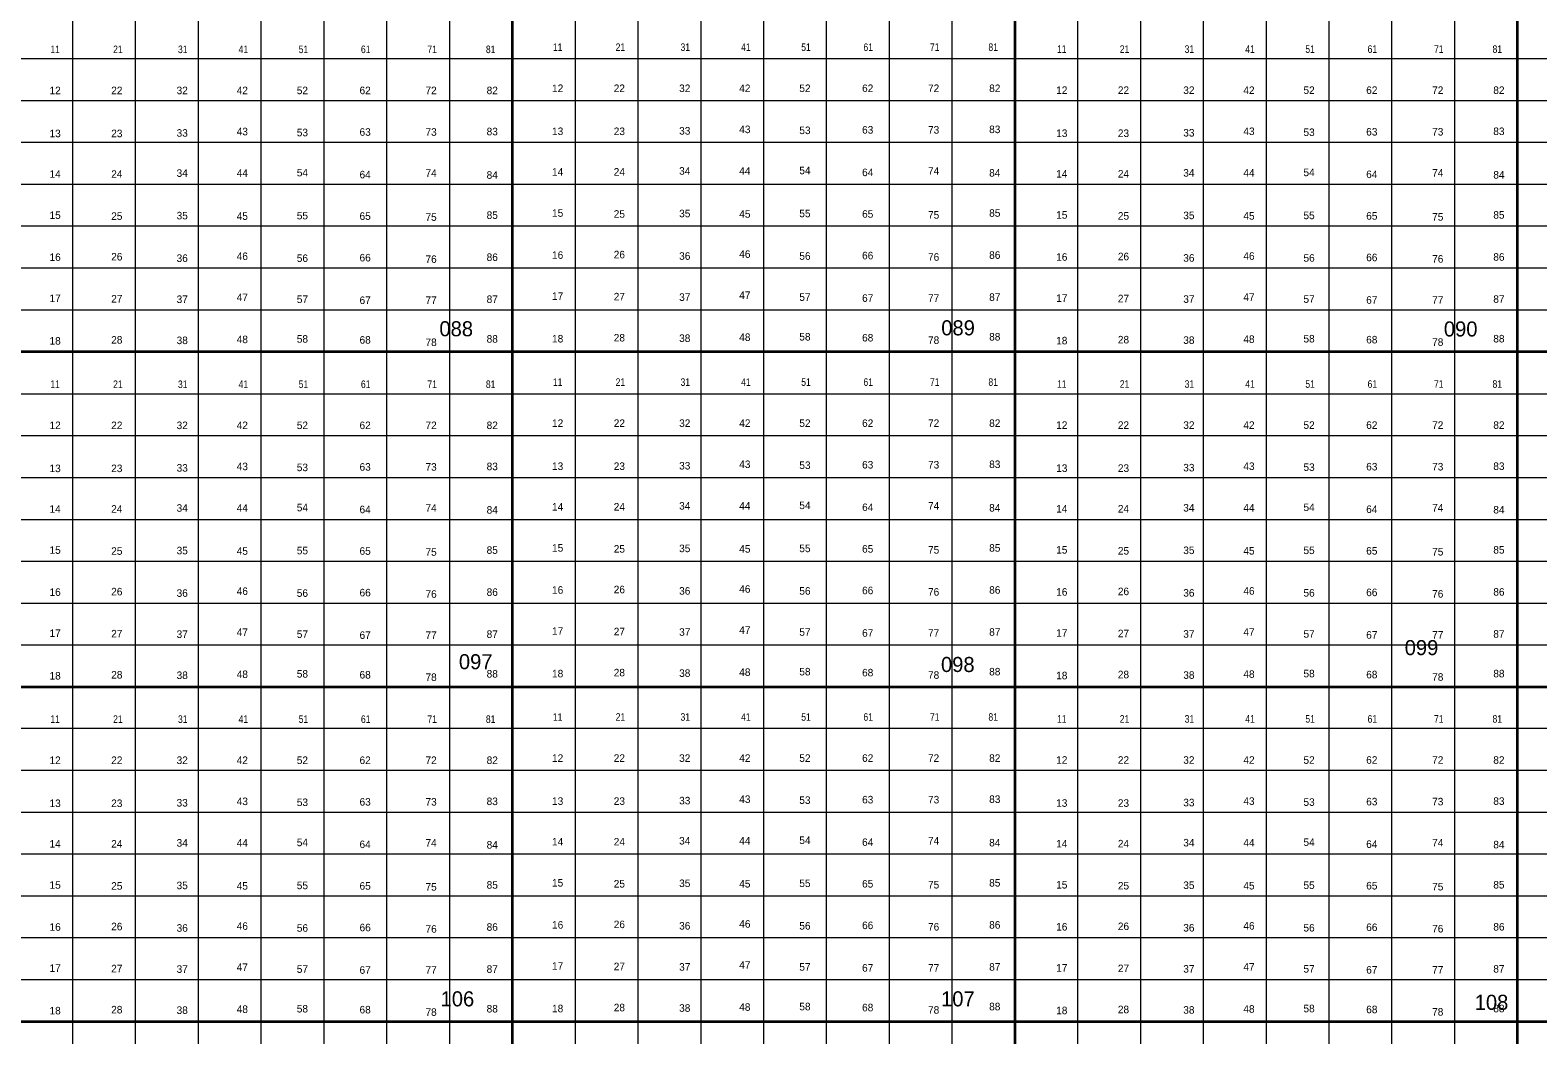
# Model space of a CAD drawing. Extents: x 639000 to 672000, y 222000 to 252000.
# Drawn here: x 651120 to 660121, y 227921 to 233921 of the extents above; entities that cross this region are included whole.
import ezdxf
from ezdxf.enums import TextEntityAlignment as Align

# ---------------------------------------------------------------- set-up
doc = ezdxf.new("R2010")
doc.units = 0
doc.header["$LTSCALE"] = 18
doc.layers.add('1', color=7, linetype='Continuous', lineweight=13)
doc.layers.add('2', color=7, linetype='Continuous')
doc.layers.add('29', color=7, linetype='Continuous')

msp = doc.modelspace()

# ---------------------------------------------------------------- linework, layer by layer
at = {"layer": '1'}
for p, q in [((651375, 224000), (651375, 252000)), ((651750, 224000), (651750, 252000)), ((652125, 224000), (652125, 252000)), ((652500, 224000), (652500, 252000)), ((652875, 224000), (652875, 252000)), ((653250, 224000), (653250, 252000)), ((653625, 224000), (653625, 252000)), ((654375, 222000), (654375, 252000)), ((654750, 222000), (654750, 252000)), ((655125, 222000), (655125, 252000)), ((655500, 222000), (655500, 252000)), ((655875, 222000), (655875, 252000)), ((656250, 222000), (656250, 252000)), ((656625, 222000), (656625, 252000)), ((657375, 222000), (657375, 248000)), ((657750, 222000), (657750, 248000)), ((658125, 222000), (658125, 248000)), ((658500, 222000), (658500, 248000)), ((658875, 222000), (658875, 248000)), ((659250, 222000), (659250, 248000)), ((659625, 222000), (659625, 248000)), ((669000, 233750), (642000, 233750)), ((669000, 233500), (642000, 233500)), ((669000, 233250), (642000, 233250)), ((669000, 233000), (642000, 233000)), ((669000, 232750), (642000, 232750)), ((669000, 232500), (642000, 232500)), ((669000, 232250), (642000, 232250)), ((642000, 231750), (669000, 231750)), ((642000, 231500), (669000, 231500)), ((642000, 231250), (669000, 231250)), ((642000, 231000), (669000, 231000)), ((642000, 230750), (669000, 230750)), ((642000, 230500), (669000, 230500)), ((642000, 230250), (669000, 230250)), ((663000, 229750), (642000, 229750)), ((663000, 229500), (642000, 229500)), ((663000, 229250), (642000, 229250)), ((663000, 229000), (642000, 229000)), ((663000, 228750), (642000, 228750)), ((663000, 228500), (642000, 228500)), ((663000, 228250), (642000, 228250))]:
    msp.add_line(p, q, dxfattribs=at)
at = {"layer": '1', "lineweight": 35}
for p, q in [((654000, 222000), (654000, 252000)), ((657000, 222000), (657000, 252000)), ((660000, 222000), (660000, 248000)), ((669000, 232000), (642000, 232000)), ((642000, 230000), (669000, 230000)), ((663000, 228000), (642000, 228000))]:
    msp.add_line(p, q, dxfattribs=at)

# ---------------------------------------------------------------- texts
at = {"layer": '2'}
for s, p in [('088', (653663.61, 232093.25)), ('089', (656659.61, 232098.74)), ('090', (659660.01, 232091.88)), ('099', (659426.17, 230189.03)), ('097', (653779.93, 230104.88)), ('098', (656657.97, 230088.3)), ('106', (653670.76, 228091.57)), ('107', (656658.37, 228091.57))]:
    msp.add_text(s, height=90, rotation=359.94, dxfattribs=at).set_placement(p, align=Align.CENTER)
msp.add_text('108', height=90, dxfattribs=at).set_placement((659844.15, 228070.86), align=Align.CENTER)
at = {"layer": '29', "width": 0.85}
for s, p in [('11', (654269.27, 233797.21)), ('21', (654643.88, 233797.21)), ('31', (655031.18, 233797.21)), ('41', (655393.08, 233797.21)), ('51', (655751.81, 233797.21)), ('61', (656123.24, 233797.21)), ('71', (656520.07, 233797.21)), ('81', (656869.28, 233797.21)), ('11', (651269.26, 233784.35)), ('21', (651643.86, 233784.35)), ('31', (652031.16, 233784.35)), ('41', (652393.07, 233784.35)), ('51', (652751.8, 233784.35)), ('61', (653123.23, 233784.35)), ('71', (653520.05, 233784.35)), ('81', (653869.26, 233784.35)), ('11', (657278.8, 233785.66)), ('21', (657653.4, 233785.66)), ('31', (658040.7, 233785.66)), ('41', (658402.61, 233785.66)), ('51', (658761.34, 233785.66)), ('61', (659132.77, 233785.66)), ('71', (659529.6, 233785.66)), ('81', (659878.8, 233785.66)), ('11', (651269.26, 231784.35)), ('21', (651643.86, 231784.35)), ('31', (652031.16, 231784.35)), ('41', (652393.07, 231784.35)), ('51', (652751.8, 231784.35)), ('61', (653123.23, 231784.35)), ('71', (653520.05, 231784.35)), ('81', (653869.26, 231784.35)), ('11', (654269.27, 231797.21)), ('21', (654643.88, 231797.21)), ('31', (655031.18, 231797.21)), ('41', (655393.08, 231797.21)), ('51', (655751.81, 231797.21)), ('61', (656123.24, 231797.21)), ('71', (656520.07, 231797.21)), ('81', (656869.28, 231797.21)), ('11', (657278.8, 231785.66)), ('21', (657653.4, 231785.66)), ('31', (658040.7, 231785.66)), ('41', (658402.61, 231785.66)), ('51', (658761.34, 231785.66)), ('61', (659132.77, 231785.66)), ('71', (659529.6, 231785.66)), ('81', (659878.8, 231785.66)), ('11', (651269.26, 229784.35)), ('21', (651643.86, 229784.35)), ('31', (652031.16, 229784.35)), ('41', (652393.07, 229784.35)), ('51', (652751.8, 229784.35)), ('61', (653123.23, 229784.35)), ('71', (653520.05, 229784.35)), ('81', (653869.26, 229784.35)), ('11', (654269.27, 229797.21)), ('21', (654643.88, 229797.21)), ('31', (655031.18, 229797.21)), ('41', (655393.08, 229797.21)), ('51', (655751.81, 229797.21)), ('61', (656123.24, 229797.21)), ('71', (656520.07, 229797.21)), ('81', (656869.28, 229797.21)), ('11', (657278.8, 229785.66)), ('21', (657653.4, 229785.66)), ('31', (658040.7, 229785.66)), ('41', (658402.61, 229785.66)), ('51', (658761.34, 229785.66)), ('61', (659132.77, 229785.66)), ('71', (659529.6, 229785.66)), ('81', (659878.8, 229785.66))]:
    msp.add_text(s, height=45, dxfattribs=at).set_placement(p, align=Align.CENTER)
at = {"layer": '29'}
for s, p in [('12', (651269.25, 233538.96)), ('22', (651637.51, 233538.96)), ('32', (652027.99, 233538.96)), ('42', (652386.72, 233538.96)), ('52', (652745.45, 233538.96)), ('62', (653120.05, 233538.96)), ('72', (653513.7, 233538.96)), ('82', (653878.78, 233538.96)), ('12', (654269.27, 233551.82)), ('22', (654637.53, 233551.82)), ('32', (655028, 233551.82)), ('42', (655386.73, 233551.82)), ('52', (655745.46, 233551.82)), ('62', (656120.07, 233551.82)), ('72', (656513.72, 233551.82)), ('82', (656878.8, 233551.82)), ('12', (657278.8, 233540.27)), ('22', (657647.05, 233540.27)), ('32', (658037.53, 233540.27)), ('42', (658396.26, 233540.27)), ('52', (658754.99, 233540.27)), ('62', (659129.59, 233540.27)), ('72', (659523.24, 233540.27)), ('82', (659888.32, 233540.27)), ('13', (651269.26, 233282.02)), ('23', (651637.51, 233282.02)), ('33', (652027.99, 233284.91)), ('43', (652386.72, 233293.57)), ('53', (652745.45, 233287.8)), ('63', (653120.05, 233290.68)), ('73', (653513.7, 233290.68)), ('83', (653878.78, 233293.57)), ('13', (654269.27, 233294.88)), ('23', (654637.53, 233294.88)), ('33', (655028, 233297.77)), ('43', (655386.73, 233306.43)), ('53', (655745.46, 233300.65)), ('63', (656120.07, 233303.54)), ('73', (656513.72, 233303.54)), ('83', (656878.8, 233306.43)), ('13', (657278.8, 233283.33)), ('23', (657647.05, 233283.33)), ('33', (658037.53, 233286.22)), ('43', (658396.26, 233294.88)), ('53', (658754.99, 233289.11)), ('63', (659129.59, 233291.99)), ('73', (659523.24, 233291.99)), ('83', (659888.33, 233294.88)), ('14', (651269.26, 233039.52)), ('24', (651637.51, 233039.52)), ('34', (652027.99, 233045.29)), ('44', (652386.72, 233045.29)), ('54', (652745.45, 233048.18)), ('64', (653120.05, 233036.63)), ('74', (653513.7, 233045.29)), ('84', (653878.78, 233033.74)), ('14', (654269.27, 233052.38)), ('24', (654637.53, 233052.38)), ('34', (655028, 233058.15)), ('44', (655386.73, 233058.15)), ('54', (655745.46, 233061.04)), ('64', (656120.07, 233049.49)), ('74', (656513.72, 233058.15)), ('84', (656878.8, 233046.6)), ('14', (657278.8, 233040.83)), ('24', (657647.05, 233040.83)), ('34', (658037.53, 233046.6)), ('44', (658396.26, 233046.6)), ('54', (658754.99, 233049.49)), ('64', (659129.59, 233037.94)), ('74', (659523.24, 233046.6)), ('84', (659888.33, 233035.05)), ('15', (654269.27, 232806.98)), ('25', (654637.53, 232801.21)), ('35', (655028, 232804.1)), ('45', (655386.73, 232801.21)), ('55', (655745.46, 232804.1)), ('65', (656120.07, 232801.21)), ('85', (656878.8, 232806.99)), ('15', (651269.26, 232794.13)), ('25', (651637.51, 232788.35)), ('35', (652027.99, 232791.24)), ('45', (652386.72, 232788.35)), ('55', (652745.45, 232791.24)), ('65', (653120.05, 232788.36)), ('75', (653513.7, 232782.58)), ('85', (653878.78, 232794.13)), ('75', (656513.72, 232795.44)), ('15', (657278.8, 232795.44)), ('25', (657647.05, 232789.66)), ('35', (658037.53, 232792.55)), ('45', (658396.26, 232789.66)), ('55', (658754.99, 232792.55)), ('65', (659129.59, 232789.66)), ('75', (659523.24, 232783.89)), ('85', (659888.33, 232795.44)), ('16', (651269.26, 232542.96)), ('26', (651637.51, 232545.85)), ('36', (652027.99, 232537.19)), ('46', (652386.72, 232548.74)), ('56', (652745.45, 232537.19)), ('66', (653120.05, 232540.08)), ('76', (653513.7, 232531.42)), ('86', (653878.78, 232542.96)), ('16', (654269.27, 232555.82)), ('26', (654637.53, 232558.71)), ('36', (655028, 232550.05)), ('46', (655386.73, 232561.59)), ('56', (655745.46, 232550.05)), ('66', (656120.07, 232552.93)), ('76', (656513.72, 232544.27)), ('86', (656878.8, 232555.82)), ('16', (657278.8, 232544.27)), ('26', (657647.05, 232547.16)), ('36', (658037.53, 232538.5)), ('46', (658396.26, 232550.05)), ('56', (658754.99, 232538.5)), ('66', (659129.59, 232541.39)), ('76', (659523.24, 232532.72)), ('86', (659888.33, 232544.27)), ('17', (651269.26, 232297.57)), ('27', (651637.51, 232294.69)), ('37', (652027.99, 232291.8)), ('47', (652386.72, 232303.35)), ('57', (652745.45, 232291.8)), ('67', (653120.05, 232286.03)), ('77', (653513.7, 232286.03)), ('87', (653878.78, 232291.8)), ('17', (654269.27, 232310.43)), ('27', (654637.53, 232307.54)), ('37', (655028, 232304.66)), ('47', (655386.73, 232316.2)), ('57', (655745.46, 232304.66)), ('67', (656120.07, 232298.88)), ('77', (656513.72, 232298.88)), ('87', (656878.8, 232304.66)), ('17', (657278.8, 232298.88)), ('27', (657647.05, 232295.99)), ('37', (658037.53, 232293.11)), ('47', (658396.26, 232304.65)), ('57', (658754.99, 232293.11)), ('67', (659129.59, 232287.33)), ('77', (659523.25, 232287.33)), ('87', (659888.33, 232293.11)), ('18', (651269.25, 232043.52)), ('28', (651637.51, 232049.3)), ('38', (652027.99, 232046.41)), ('48', (652386.72, 232052.18)), ('58', (652745.45, 232055.07)), ('68', (653120.05, 232049.3)), ('78', (653513.7, 232034.86)), ('88', (653878.78, 232055.07)), ('18', (654269.27, 232056.38)), ('28', (654637.53, 232062.15)), ('38', (655028, 232059.27)), ('48', (655386.73, 232065.04)), ('58', (655745.46, 232067.93)), ('68', (656120.07, 232062.15)), ('78', (656513.72, 232047.72)), ('88', (656878.8, 232067.93)), ('18', (657278.8, 232044.83)), ('28', (657647.05, 232050.6)), ('38', (658037.53, 232047.72)), ('48', (658396.26, 232053.49)), ('58', (658754.99, 232056.38)), ('68', (659129.59, 232050.6)), ('78', (659523.24, 232036.17)), ('88', (659888.32, 232056.38)), ('12', (654269.27, 231551.82)), ('22', (654637.53, 231551.82)), ('32', (655028, 231551.82)), ('42', (655386.73, 231551.82)), ('52', (655745.46, 231551.82)), ('62', (656120.07, 231551.82)), ('72', (656513.72, 231551.82)), ('82', (656878.8, 231551.82)), ('12', (657278.8, 231540.27)), ('22', (657647.05, 231540.27)), ('32', (658037.53, 231540.27)), ('42', (658396.26, 231540.27)), ('52', (658754.99, 231540.27)), ('62', (659129.59, 231540.27)), ('72', (659523.24, 231540.27)), ('82', (659888.32, 231540.27)), ('12', (651269.25, 231538.96)), ('22', (651637.51, 231538.96)), ('32', (652027.99, 231538.96)), ('42', (652386.72, 231538.96)), ('52', (652745.45, 231538.96)), ('62', (653120.05, 231538.96)), ('72', (653513.7, 231538.96)), ('82', (653878.78, 231538.96)), ('13', (651269.26, 231282.02)), ('23', (651637.51, 231282.02)), ('33', (652027.99, 231284.91)), ('43', (652386.72, 231293.57)), ('53', (652745.45, 231287.8)), ('63', (653120.05, 231290.68)), ('73', (653513.7, 231290.68)), ('83', (653878.78, 231293.57)), ('13', (654269.27, 231294.88)), ('23', (654637.53, 231294.88)), ('33', (655028, 231297.77)), ('43', (655386.73, 231306.43)), ('53', (655745.46, 231300.65)), ('63', (656120.07, 231303.54)), ('73', (656513.72, 231303.54)), ('83', (656878.8, 231306.43)), ('13', (657278.8, 231283.33)), ('23', (657647.05, 231283.33)), ('33', (658037.53, 231286.22)), ('43', (658396.26, 231294.88)), ('53', (658754.99, 231289.11)), ('63', (659129.59, 231291.99)), ('73', (659523.24, 231291.99)), ('83', (659888.33, 231294.88)), ('14', (651269.26, 231039.52)), ('24', (651637.51, 231039.52)), ('34', (652027.99, 231045.29)), ('44', (652386.72, 231045.29)), ('54', (652745.45, 231048.18)), ('64', (653120.05, 231036.63)), ('74', (653513.7, 231045.29)), ('84', (653878.78, 231033.74)), ('14', (654269.27, 231052.38)), ('24', (654637.53, 231052.38)), ('34', (655028, 231058.15)), ('44', (655386.73, 231058.15)), ('54', (655745.46, 231061.04)), ('64', (656120.07, 231049.49)), ('74', (656513.72, 231058.15)), ('84', (656878.8, 231046.6)), ('14', (657278.8, 231040.83)), ('24', (657647.05, 231040.83)), ('34', (658037.53, 231046.6)), ('44', (658396.26, 231046.6)), ('54', (658754.99, 231049.49)), ('64', (659129.59, 231037.94)), ('74', (659523.24, 231046.6)), ('84', (659888.33, 231035.05)), ('15', (651269.26, 230794.13)), ('25', (651637.51, 230788.35)), ('35', (652027.99, 230791.24)), ('45', (652386.72, 230788.35)), ('55', (652745.45, 230791.24)), ('65', (653120.05, 230788.36)), ('75', (653513.7, 230782.58)), ('85', (653878.78, 230794.13)), ('15', (654269.27, 230806.98)), ('25', (654637.53, 230801.21)), ('35', (655028, 230804.1)), ('45', (655386.73, 230801.21)), ('55', (655745.46, 230804.1)), ('65', (656120.07, 230801.21)), ('75', (656513.72, 230795.44)), ('85', (656878.8, 230806.99)), ('15', (657278.8, 230795.44)), ('25', (657647.05, 230789.66)), ('35', (658037.53, 230792.55)), ('45', (658396.26, 230789.66)), ('55', (658754.99, 230792.55)), ('65', (659129.59, 230789.66)), ('75', (659523.24, 230783.89)), ('85', (659888.33, 230795.44)), ('16', (654269.27, 230555.82)), ('26', (654637.53, 230558.71)), ('36', (655028, 230550.05)), ('46', (655386.73, 230561.59)), ('56', (655745.46, 230550.05)), ('66', (656120.07, 230552.93)), ('86', (656878.8, 230555.82)), ('46', (658396.26, 230550.05)), ('16', (651269.26, 230542.96)), ('26', (651637.51, 230545.85)), ('36', (652027.99, 230537.19)), ('46', (652386.72, 230548.74)), ('56', (652745.45, 230537.19)), ('66', (653120.05, 230540.08)), ('76', (653513.7, 230531.42)), ('86', (653878.78, 230542.96)), ('76', (656513.72, 230544.27)), ('16', (657278.8, 230544.27)), ('26', (657647.05, 230547.16)), ('36', (658037.53, 230538.5)), ('56', (658754.99, 230538.5)), ('66', (659129.59, 230541.39)), ('76', (659523.24, 230532.72)), ('86', (659888.33, 230544.27)), ('17', (651269.26, 230297.57)), ('27', (651637.51, 230294.69)), ('37', (652027.99, 230291.8)), ('47', (652386.72, 230303.35)), ('57', (652745.45, 230291.8)), ('67', (653120.05, 230286.03)), ('77', (653513.7, 230286.03)), ('87', (653878.78, 230291.8)), ('17', (654269.27, 230310.43)), ('27', (654637.53, 230307.54)), ('37', (655028, 230304.66)), ('47', (655386.73, 230316.2)), ('57', (655745.46, 230304.66)), ('67', (656120.07, 230298.88)), ('77', (656513.72, 230298.88)), ('87', (656878.8, 230304.66)), ('17', (657278.8, 230298.88)), ('27', (657647.05, 230295.99)), ('37', (658037.53, 230293.11)), ('47', (658396.26, 230304.65)), ('57', (658754.99, 230293.11)), ('67', (659129.59, 230287.33)), ('77', (659523.25, 230287.33)), ('87', (659888.33, 230293.11)), ('18', (651269.25, 230043.52)), ('28', (651637.51, 230049.3)), ('38', (652027.99, 230046.41)), ('48', (652386.72, 230052.18)), ('58', (652745.45, 230055.07)), ('68', (653120.05, 230049.3)), ('78', (653513.7, 230034.86)), ('88', (653878.78, 230055.07)), ('18', (654269.27, 230056.38)), ('28', (654637.53, 230062.15)), ('38', (655028, 230059.27)), ('48', (655386.73, 230065.04)), ('58', (655745.46, 230067.93)), ('68', (656120.07, 230062.15)), ('78', (656513.72, 230047.72)), ('88', (656878.8, 230067.93)), ('18', (657278.8, 230044.83)), ('28', (657647.05, 230050.6)), ('38', (658037.53, 230047.72)), ('48', (658396.26, 230053.49)), ('58', (658754.99, 230056.38)), ('68', (659129.59, 230050.6)), ('78', (659523.24, 230036.17)), ('88', (659888.32, 230056.38)), ('12', (651269.25, 229538.96)), ('22', (651637.51, 229538.96)), ('32', (652027.99, 229538.96)), ('42', (652386.72, 229538.96)), ('52', (652745.45, 229538.96)), ('62', (653120.05, 229538.96)), ('72', (653513.7, 229538.96)), ('82', (653878.78, 229538.96)), ('12', (654269.27, 229551.82)), ('22', (654637.53, 229551.82)), ('32', (655028, 229551.82)), ('42', (655386.73, 229551.82)), ('52', (655745.46, 229551.82)), ('62', (656120.07, 229551.82)), ('72', (656513.72, 229551.82)), ('82', (656878.8, 229551.82)), ('12', (657278.8, 229540.27)), ('22', (657647.05, 229540.27)), ('32', (658037.53, 229540.27)), ('42', (658396.26, 229540.27)), ('52', (658754.99, 229540.27)), ('62', (659129.59, 229540.27)), ('72', (659523.24, 229540.27)), ('82', (659888.32, 229540.27)), ('43', (652386.72, 229293.57)), ('63', (653120.05, 229290.68)), ('73', (653513.7, 229290.68)), ('83', (653878.78, 229293.57)), ('13', (654269.27, 229294.88)), ('23', (654637.53, 229294.88)), ('33', (655028, 229297.77)), ('43', (655386.73, 229306.43)), ('53', (655745.46, 229300.65)), ('63', (656120.07, 229303.54)), ('73', (656513.72, 229303.54)), ('83', (656878.8, 229306.43)), ('43', (658396.26, 229294.88)), ('63', (659129.59, 229291.99)), ('73', (659523.24, 229291.99)), ('83', (659888.33, 229294.88)), ('13', (651269.26, 229282.02)), ('23', (651637.51, 229282.02)), ('33', (652027.99, 229284.91)), ('53', (652745.45, 229287.8)), ('13', (657278.8, 229283.33)), ('23', (657647.05, 229283.33)), ('33', (658037.53, 229286.22)), ('53', (658754.99, 229289.11)), ('14', (651269.26, 229039.52)), ('24', (651637.51, 229039.52)), ('34', (652027.99, 229045.29)), ('44', (652386.72, 229045.29)), ('54', (652745.45, 229048.18)), ('64', (653120.05, 229036.63)), ('74', (653513.7, 229045.29)), ('84', (653878.78, 229033.74)), ('14', (654269.27, 229052.38)), ('24', (654637.53, 229052.38)), ('34', (655028, 229058.15)), ('44', (655386.73, 229058.15)), ('54', (655745.46, 229061.04)), ('64', (656120.07, 229049.49)), ('74', (656513.72, 229058.15)), ('84', (656878.8, 229046.6)), ('14', (657278.8, 229040.83)), ('24', (657647.05, 229040.83)), ('34', (658037.53, 229046.6)), ('44', (658396.26, 229046.6)), ('54', (658754.99, 229049.49)), ('64', (659129.59, 229037.94)), ('74', (659523.24, 229046.6)), ('84', (659888.33, 229035.05)), ('15', (651269.26, 228794.13)), ('25', (651637.51, 228788.35)), ('35', (652027.99, 228791.24)), ('45', (652386.72, 228788.35)), ('55', (652745.45, 228791.24)), ('65', (653120.05, 228788.36)), ('75', (653513.7, 228782.58)), ('85', (653878.78, 228794.13)), ('15', (654269.27, 228806.98)), ('25', (654637.53, 228801.21)), ('35', (655028, 228804.1)), ('45', (655386.73, 228801.21)), ('55', (655745.46, 228804.1)), ('65', (656120.07, 228801.21)), ('75', (656513.72, 228795.44)), ('85', (656878.8, 228806.99)), ('15', (657278.8, 228795.44)), ('25', (657647.05, 228789.66)), ('35', (658037.53, 228792.55)), ('45', (658396.26, 228789.66)), ('55', (658754.99, 228792.55)), ('65', (659129.59, 228789.66)), ('75', (659523.24, 228783.89)), ('85', (659888.33, 228795.44)), ('16', (651269.26, 228542.96)), ('26', (651637.51, 228545.85)), ('36', (652027.99, 228537.19)), ('46', (652386.72, 228548.74)), ('56', (652745.45, 228537.19)), ('66', (653120.05, 228540.08)), ('76', (653513.7, 228531.42)), ('86', (653878.78, 228542.96)), ('16', (654269.27, 228555.82)), ('26', (654637.53, 228558.71)), ('36', (655028, 228550.05)), ('46', (655386.73, 228561.59)), ('56', (655745.46, 228550.05)), ('66', (656120.07, 228552.93)), ('76', (656513.72, 228544.27)), ('86', (656878.8, 228555.82)), ('16', (657278.8, 228544.27)), ('26', (657647.05, 228547.16)), ('36', (658037.53, 228538.5)), ('46', (658396.26, 228550.05)), ('56', (658754.99, 228538.5)), ('66', (659129.59, 228541.39)), ('76', (659523.24, 228532.72)), ('86', (659888.33, 228544.27)), ('47', (652386.72, 228303.35)), ('17', (654269.27, 228310.43)), ('27', (654637.53, 228307.54)), ('37', (655028, 228304.66)), ('47', (655386.73, 228316.2)), ('57', (655745.46, 228304.66)), ('87', (656878.8, 228304.66)), ('47', (658396.26, 228304.65)), ('17', (651269.26, 228297.57)), ('27', (651637.51, 228294.69)), ('37', (652027.99, 228291.8)), ('57', (652745.45, 228291.8)), ('67', (653120.05, 228286.03)), ('77', (653513.7, 228286.03)), ('87', (653878.78, 228291.8)), ('67', (656120.07, 228298.88)), ('77', (656513.72, 228298.88)), ('17', (657278.8, 228298.88)), ('27', (657647.05, 228295.99)), ('37', (658037.53, 228293.11)), ('57', (658754.99, 228293.11)), ('67', (659129.59, 228287.33)), ('77', (659523.25, 228287.33)), ('87', (659888.33, 228293.11)), ('18', (651269.25, 228043.52)), ('28', (651637.51, 228049.3)), ('38', (652027.99, 228046.41)), ('48', (652386.72, 228052.18)), ('58', (652745.45, 228055.07)), ('68', (653120.05, 228049.3)), ('78', (653513.7, 228034.86)), ('88', (653878.78, 228055.07)), ('18', (654269.27, 228056.38)), ('28', (654637.53, 228062.15)), ('38', (655028, 228059.27)), ('48', (655386.73, 228065.04)), ('58', (655745.46, 228067.93)), ('68', (656120.07, 228062.15)), ('78', (656513.72, 228047.72)), ('88', (656878.8, 228067.93)), ('18', (657278.8, 228044.83)), ('28', (657647.05, 228050.6)), ('38', (658037.53, 228047.72)), ('48', (658396.26, 228053.49)), ('58', (658754.99, 228056.38)), ('68', (659129.59, 228050.6)), ('78', (659523.24, 228036.17)), ('88', (659888.32, 228056.38))]:
    msp.add_text(s, height=45, dxfattribs=at).set_placement(p, align=Align.CENTER)

doc.saveas('drawing.dxf')
